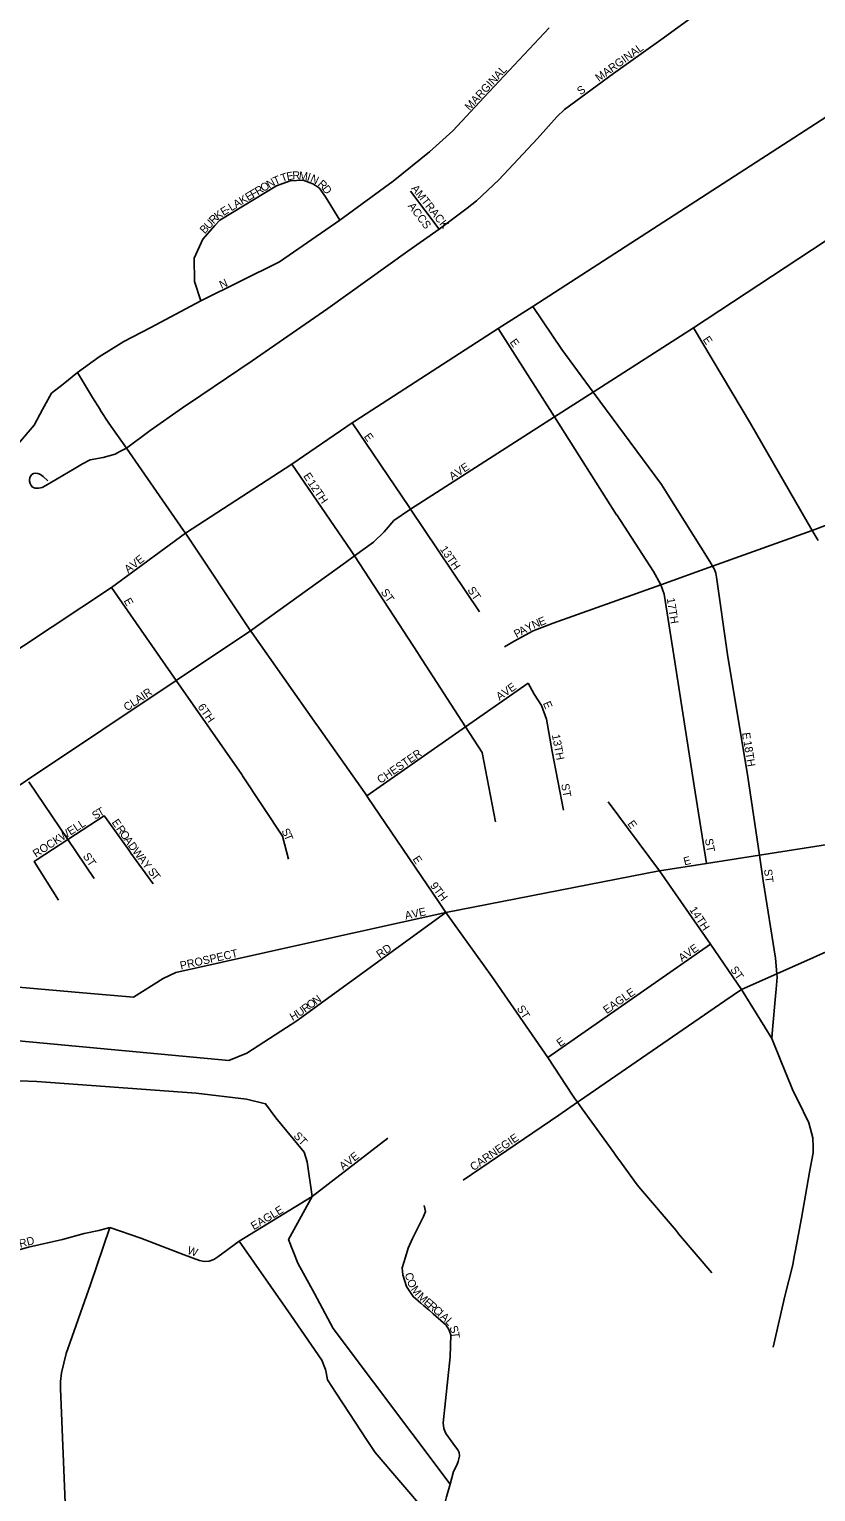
# Model space of a CAD drawing. Extents: x 0 to 96.2, y -27.5 to 31.3.
# Drawn here: x 4.744 to 5.674, y 18.275 to 20.006 of the extents above; entities that cross this region are included whole.
import ezdxf

# ---------------------------------------------------------------- set-up
doc = ezdxf.new("R2010")
doc.units = 0
doc.layers.add('TB_PP_20x10_GRID', color=7, linetype='Continuous')
doc.layers.add('TB_PP_30x10', color=7, linetype='Continuous')

msp = doc.modelspace()

# ---------------------------------------------------------------- linework, layer by layer
at = {"layer": 'TB_PP_20x10_GRID'}
for points in [[(5.1917, 19.7434), (5.2285, 19.7696), (5.2616, 19.7942), (5.2728, 19.8031), (5.2992, 19.828), (5.3449, 19.8768), (5.3677, 19.9026), (5.3768, 19.911), (5.4349, 19.9537), (5.4909, 19.9938), (5.5353, 20.0261)], [(5.3586, 20.0078), (5.282, 19.9258), (5.2448, 19.8858), (5.2172, 19.861), (5.174, 19.8264), (5.1109, 19.7801), (5.0399, 19.7307), (4.9467, 19.6847), (4.8868, 19.6529), (4.8556, 19.6364), (4.8263, 19.6186), (4.8006, 19.5998)], [(5.1289, 19.5424), (5.2984, 19.6518), (5.3392, 19.6781), (5.7386, 19.9359)], [(5.1934, 19.4374), (5.1947, 19.4383), (5.3649, 19.5473), (5.4108, 19.5767), (5.5294, 19.6527), (5.7001, 19.765), (5.8056, 19.8313), (5.8853, 19.8833), (5.8926, 19.888), (5.9149, 19.9019), (5.9668, 19.9359)], [(5.306, 19.2752), (5.3175, 19.2818), (5.3396, 19.294), (5.3633, 19.303), (5.4908, 19.3487), (5.552, 19.3706), (5.6699, 19.4129), (5.8766, 19.4911), (5.987, 19.5341), (6.1189, 19.5852), (6.5959, 19.7707), (6.9729, 19.9173)], [(5.1109, 19.7801), (5.0943, 19.8078), (5.0865, 19.8183), (5.0793, 19.823), (5.0677, 19.8275), (5.0522, 19.8266), (5.0361, 19.8208), (4.9691, 19.7802), (4.9633, 19.7737)], [(5.2285, 19.7696), (5.1947, 19.8145)], [(4.9633, 19.7737), (4.9489, 19.7576), (4.9388, 19.7351), (4.9391, 19.7074), (4.9467, 19.6847)], [(4.9251, 19.5579), (4.9465, 19.5727), (5.0074, 19.6137), (5.097, 19.6756), (5.1917, 19.7434)], [(5.4108, 19.5767), (5.3735, 19.6272), (5.3392, 19.6781)], [(5.4386, 19.4314), (5.4385, 19.4315), (5.3649, 19.5473), (5.2984, 19.6518)], [(5.677, 19.401), (5.6699, 19.4129), (5.5968, 19.5395), (5.5294, 19.6527)], [(4.608, 19.4727), (4.6213, 19.4537), (4.6356, 19.4511), (4.6765, 19.4758), (4.7067, 19.497), (4.7309, 19.5157), (4.7496, 19.5375), (4.7593, 19.5562), (4.7701, 19.5754), (4.784, 19.5861), (4.8006, 19.5998)], [(4.8066, 19.59), (4.8006, 19.5998)], [(4.8281, 19.5551), (4.8274, 19.5562), (4.8187, 19.5703), (4.8066, 19.59)], [(5.4996, 19.4546), (5.4917, 19.4672), (5.4108, 19.5767)], [(4.838, 19.5401), (4.8281, 19.5551)], [(4.8501, 19.5058), (4.8586, 19.5105), (4.8868, 19.5314), (4.9251, 19.5579)], [(4.5743, 19.1717), (4.6662, 19.2297), (4.8411, 19.3455), (4.9286, 19.4096), (5.0545, 19.4913), (5.1255, 19.5402), (5.1289, 19.5424)], [(4.9263, 19.4129), (4.8586, 19.5105), (4.838, 19.5401)], [(5.1928, 19.4411), (5.1255, 19.5402)], [(4.7658, 19.4715), (4.76, 19.4767), (4.76, 19.4768), (4.757, 19.479), (4.7537, 19.4805), (4.7514, 19.4807), (4.7488, 19.4803), (4.7468, 19.4791), (4.7453, 19.4772), (4.7444, 19.4752), (4.7441, 19.4733), (4.7441, 19.4711), (4.7447, 19.4684), (4.7459, 19.4662), (4.7477, 19.4641), (4.7508, 19.4629), (4.755, 19.4628), (4.759, 19.4639), (4.7634, 19.4661), (4.7969, 19.486), (4.8067, 19.4916), (4.8158, 19.4965), (4.8312, 19.4994), (4.8454, 19.5032), (4.8501, 19.5058)], [(5.0545, 19.4913), (5.1246, 19.3888)], [(5.2762, 19.3167), (5.1947, 19.4383), (5.1928, 19.4411)], [(5.6266, 18.8617), (5.6274, 18.8702), (5.6283, 18.8843), (5.628, 18.8881), (5.6265, 18.9067), (5.612, 18.9983), (5.6074, 19.0287), (5.5936, 19.1212), (5.5695, 19.2662), (5.5568, 19.3575), (5.5559, 19.3623), (5.5544, 19.3666), (5.552, 19.3706), (5.5488, 19.376), (5.4996, 19.4546)], [(5.1176, 19.375), (5.1286, 19.383), (5.151, 19.3991), (5.1637, 19.4113), (5.175, 19.4246), (5.1934, 19.4374)], [(5.5073, 19.2573), (5.4948, 19.3376), (5.4908, 19.3487), (5.4906, 19.3493), (5.4822, 19.3645), (5.4386, 19.4314)], [(5.007, 19.2922), (5.0055, 19.2943), (4.9286, 19.4096), (4.9263, 19.4129)], [(5.1246, 19.3888), (5.1286, 19.383), (5.2036, 19.2673)], [(5.0055, 19.2943), (5.1176, 19.375)], [(4.995, 19.1239), (4.9176, 19.2354), (4.8411, 19.3455)], [(4.4808, 18.9427), (4.565, 18.9991), (4.6509, 19.0567), (4.7418, 19.1176), (4.9176, 19.2354), (5.0055, 19.2943)], [(5.0849, 19.1814), (5.0836, 19.1833), (5.007, 19.2922)], [(5.2036, 19.2673), (5.204, 19.2667), (5.2598, 19.1805)], [(5.5303, 19.1108), (5.5073, 19.2573)], [(5.143, 19.0987), (5.2598, 19.1805), (5.3338, 19.2323)], [(5.3756, 19.0818), (5.3624, 19.1512), (5.3557, 19.1897), (5.3498, 19.2057), (5.341, 19.2193), (5.3338, 19.2323)], [(5.1405, 19.1022), (5.0865, 19.1791), (5.0849, 19.1814)], [(5.2598, 19.1805), (5.2795, 19.1502), (5.2954, 19.0679)], [(4.8205, 19.001), (4.7894, 19.0472), (4.7433, 19.1154)], [(5.0504, 19.0238), (5.0434, 19.0509), (4.996, 19.1226), (4.995, 19.1239)], [(5.5447, 19.0189), (5.5303, 19.1108)], [(5.1787, 19.0462), (5.1443, 19.0967), (5.143, 19.0987), (5.1405, 19.1022)], [(5.5863, 18.8695), (5.5496, 18.9233), (5.4892, 19.0102), (5.4285, 19.0916)], [(4.8337, 19.0733), (4.8323, 19.0752), (4.7894, 19.0472), (4.7531, 19.0236)], [(4.8619, 19.034), (4.8337, 19.0733)], [(5.4887, 19.0101), (5.4892, 19.0102), (5.5447, 19.0189), (5.6074, 19.0287), (5.7659, 19.0535), (5.8206, 19.062)], [(5.2287, 18.9725), (5.1787, 19.0462)], [(4.7531, 19.0236), (4.7496, 19.0213), (4.7782, 18.9755)], [(4.8901, 18.9946), (4.8639, 19.0311), (4.8619, 19.034)], [(5.078, 18.9257), (5.2366, 18.9608), (5.4887, 19.0101)], [(5.3862, 18.7445), (5.3571, 18.7892), (5.2909, 18.8849), (5.2366, 18.9608), (5.2287, 18.9725)], [(5.0634, 18.8349), (5.2366, 18.9608)], [(4.9021, 18.8825), (4.9169, 18.8899), (5.078, 18.9257)], [(5.3571, 18.7892), (5.5496, 18.9233)], [(5.3946, 18.7378), (5.5667, 18.8561), (5.5863, 18.8695), (5.628, 18.8881), (5.7182, 18.9282), (5.7299, 18.9337)], [(4.6455, 18.8834), (4.6634, 18.8781), (4.8069, 18.8658)], [(4.8069, 18.8658), (4.8672, 18.8607), (4.9021, 18.8825)], [(5.622, 18.8115), (5.6137, 18.825), (5.5863, 18.8695)], [(5.622, 18.8115), (5.623, 18.8224), (5.6266, 18.8617)], [(5.0479, 18.8246), (5.0604, 18.8327), (5.0634, 18.8349)], [(4.5662, 18.8241), (4.9798, 18.7855), (5.0011, 18.7941)], [(5.0011, 18.7941), (5.0479, 18.8246)], [(5.6407, 18.7658), (5.6336, 18.7832), (5.622, 18.8115)], [(5.671, 18.6829), (5.6708, 18.6942), (5.666, 18.7119), (5.6529, 18.7385), (5.6475, 18.7491), (5.645, 18.7552), (5.6407, 18.7658)], [(4.5436, 18.7057), (4.5862, 18.7359), (4.6832, 18.7567), (4.7123, 18.7622), (4.7525, 18.7608), (4.941, 18.747), (5.0005, 18.74), (5.0233, 18.7344), (5.0355, 18.7177), (5.0687, 18.677), (5.0723, 18.6657), (5.0784, 18.6246), (5.0504, 18.5737), (5.0615, 18.5459), (5.0812, 18.5098), (5.1031, 18.4683), (5.1509, 18.4047), (5.2415, 18.2842)], [(5.2568, 18.6438), (5.37, 18.7209), (5.3921, 18.7361), (5.3946, 18.7378)], [(5.4374, 18.6731), (5.4351, 18.6765), (5.4124, 18.7081), (5.3977, 18.7284), (5.3921, 18.7361), (5.3886, 18.7409), (5.3862, 18.7445)], [(4.9269, 18.5556), (4.9449, 18.5487), (4.9506, 18.5477), (4.9567, 18.5479), (4.9621, 18.5499), (4.9668, 18.5532), (4.9922, 18.5716), (5.0784, 18.6246), (5.1677, 18.6936)], [(5.6237, 18.4463), (5.6375, 18.5066), (5.6468, 18.5437), (5.6487, 18.5536), (5.6497, 18.5593), (5.6571, 18.5991), (5.6668, 18.6536), (5.6711, 18.6761), (5.671, 18.6829)], [(5.4692, 18.6311), (5.4629, 18.6385), (5.4441, 18.6639), (5.4374, 18.6731)], [(5.551, 18.5341), (5.5118, 18.5805), (5.5088, 18.5842), (5.4692, 18.6311)], [(5.2109, 18.6139), (5.2123, 18.6067), (5.2102, 18.6008), (5.1971, 18.575), (5.1921, 18.5635), (5.1888, 18.553), (5.1847, 18.5401), (5.1858, 18.5317), (5.19, 18.5181), (5.1979, 18.5062), (5.2068, 18.4984), (5.2104, 18.4953), (5.2162, 18.4903), (5.2215, 18.4857), (5.2368, 18.4724), (5.2402, 18.4672), (5.2422, 18.4609), (5.2415, 18.4348), (5.2334, 18.3567), (5.234, 18.35), (5.2364, 18.344), (5.248, 18.3283), (5.2506, 18.3247), (5.2521, 18.3218), (5.2524, 18.3205), (5.2527, 18.3188), (5.2526, 18.3172), (5.2523, 18.3156), (5.2511, 18.311), (5.2495, 18.3066), (5.2455, 18.299), (5.2415, 18.2842)], [(4.6708, 18.5444), (4.7429, 18.5647), (4.7832, 18.5736), (4.8087, 18.581), (4.8259, 18.5842), (4.8392, 18.588)], [(4.7867, 17.6939), (4.7863, 17.7245), (4.7771, 17.8376), (4.7736, 17.8561), (4.7785, 17.9483), (4.7867, 18.0987), (4.7877, 18.1227), (4.789, 18.1413), (4.7887, 18.1703), (4.7874, 18.2006), (4.7864, 18.2526), (4.7807, 18.3972), (4.7807, 18.4056), (4.782, 18.416), (4.7875, 18.4389), (4.816, 18.5206), (4.8392, 18.588)], [(4.8392, 18.588), (4.8757, 18.5754), (4.9269, 18.5556)], [(5.0948, 18.4164), (5.0941, 18.42), (5.0896, 18.4307), (5.053, 18.4842), (5.0468, 18.4931), (4.9922, 18.5716)], [(5.1428, 18.3371), (5.1227, 18.3678), (5.1068, 18.392), (5.0965, 18.4077), (5.0948, 18.4164)], [(5.2135, 18.2505), (5.1529, 18.3218), (5.1428, 18.3371)], [(5.2415, 18.2842), (5.2415, 18.2842), (5.2373, 18.2692), (5.236, 18.2643), (5.2342, 18.2603), (5.2313, 18.2573), (5.2274, 18.2549), (5.2135, 18.2505)]]:
    msp.add_lwpolyline(points, dxfattribs=at)

# ---------------------------------------------------------------- texts
at = {"layer": 'TB_PP_30x10'}
for s, rotation, p in [('MARGINAL', 35.8036, (5.4175, 19.9437)), ('MARGINAL', 47.3667, (5.2647, 19.9092)), ('S', 35.5436, (5.3958, 19.9278)), ('E', 10.6348, (5.0489, 19.8271)), ('R', 2.3081, (5.0551, 19.8283)), ('M', 353.1348, (5.0622, 19.8286)), ('R', 30.9372, (5.0141, 19.8094)), ('O', 30.9188, (5.0205, 19.8133)), ('N', 29.734, (5.0276, 19.8176)), ('T', 23.0443, (5.0346, 19.8216)), ('T', 19.1173, (5.0429, 19.825)), ('I', 342.3253, (5.0716, 19.8275)), ('N', 334.7058, (5.0753, 19.8263)), ('R', 317.594, (5.0843, 19.8219)), ('D', 307.4687, (5.0895, 19.8171)), ('AMTRACK', 308.5293, (5.1949, 19.8175)), ('A', 30.9188, (4.9884, 19.794)), ('K', 30.926, (4.9955, 19.7983)), ('E', 30.9378, (5.0027, 19.8026)), ('F', 30.931, (5.0084, 19.806)), ('R', 46.563, (4.962, 19.7751)), ('K', 36.2186, (4.9668, 19.7802)), ('E', 31.1887, (4.9734, 19.785)), ('-', 30.8888, (4.9791, 19.7885)), ('L', 30.9321, (4.9826, 19.7906)), ('ACCS', 307.1845, (5.1911, 19.7968)), ('B', 47.5418, (4.9513, 19.7634)), ('U', 47.5498, (4.9564, 19.7689)), ('N', 23.9738, (4.9711, 19.6988)), ('E', 305.5436, (5.3116, 19.6357)), ('E', 303.6733, (5.54, 19.639)), ('E', 305.5436, (5.1391, 19.5241)), ('AVE', 33.6901, (5.2442, 19.472)), ('E', 303.6985, (5.0675, 19.4774)), ('12TH', 304.6965, (5.0725, 19.4691)), ('13TH', 304.6965, (5.2291, 19.3907)), ('AVE', 38.0509, (4.8607, 19.3619)), ('ST', 304.6987, (5.1591, 19.3399)), ('ST', 304.6908, (5.2616, 19.3424)), ('E', 299.755, (4.8551, 19.3298)), ('17TH', 278.8832, (5.4978, 19.3325)), ('Y', 26.7508, (5.3333, 19.2926)), ('N', 23.2589, (5.3406, 19.2963)), ('E', 22.8111, (5.3482, 19.2995)), ('P', 28.545, (5.3201, 19.2854)), ('A', 28.5494, (5.326, 19.2886)), ('AVE', 35.3165, (5.3, 19.2112)), ('CLAIR', 33.9939, (4.8592, 19.1987)), ('6TH', 304.5935, (4.9425, 19.2041)), ('E', 293.2569, (5.3511, 19.2084)), ('13TH', 280.6213, (5.3619, 19.1709)), ('E', 277.1217, (5.5869, 19.1733)), ('18TH', 279.1648, (5.5886, 19.1633)), ('CHESTER', 34.4594, (5.1592, 19.1128)), ('ST', 280.6147, (5.3728, 19.1125)), ('S', 32.7582, (4.8217, 19.0703)), ('T', 29.6093, (4.8271, 19.0739)), ('ROCKWELL', 32.8703, (4.7517, 19.0254)), ('E', 304.7055, (4.8408, 19.0674)), ('R', 304.7274, (4.846, 19.0598)), ('S', 298.1416, (5.0417, 19.0573)), ('E', 305.5436, (5.4508, 19.0657)), ('O', 304.7145, (4.8503, 19.0537)), ('A', 304.7145, (4.855, 19.0468)), ('D', 305.7592, (4.8599, 19.0398)), ('T', 292.395, (5.0447, 19.0517)), ('ST', 280.6279, (5.5428, 19.0475)), ('ST', 304.6987, (4.8066, 19.0274)), ('W', 307.7272, (4.865, 19.0328)), ('A', 307.8744, (4.8716, 19.0242)), ('E', 303.6985, (5.1967, 19.024)), ('E', 14.0491, (5.5189, 19.0164)), ('Y', 307.8903, (4.8767, 19.0176)), ('S', 307.8716, (4.8834, 19.0091)), ('T', 307.8889, (4.8875, 19.0038)), ('ST', 277.1351, (5.6128, 19.0116)), ('9TH', 306.8682, (5.2174, 18.9924)), ('AVE', 12.0958, (5.189, 18.9523)), ('14TH', 303.6957, (5.5242, 18.964)), ('RD', 34.5143, (5.1583, 18.9062)), ('AVE', 35.3105, (5.5158, 18.902)), ('PROSPECT', 12.6186, (4.9231, 18.8931)), ('ST', 304.7022, (5.5725, 18.8932)), ('EAGLE', 34.8271, (5.4267, 18.8403)), ('R', 36.0182, (5.0701, 18.8417)), ('O', 36.0495, (5.0761, 18.8461)), ('N', 36.0306, (5.0829, 18.851)), ('ST', 302.7321, (5.32, 18.8473)), ('H', 30.2139, (5.0552, 18.8321)), ('U', 35.1333, (5.0631, 18.8368)), ('E', 35.5436, (5.3716, 18.8012)), ('ST', 312.5121, (5.0557, 18.6959)), ('CARNEGIE', 34.5918, (5.2692, 18.6545)), ('AVE', 38.0509, (5.1149, 18.6553)), ('EAGLE', 31.1382, (5.0093, 18.5846)), ('RD', 14.7447, (4.733, 18.5639)), ('W', 341.5596, (4.9299, 18.5572)), ('C', 283.5061, (5.1879, 18.5333)), ('O', 292.9245, (5.1901, 18.5244)), ('M', 306.1702, (5.1946, 18.5146)), ('M', 318.6731, (5.202, 18.5049)), ('E', 320.0084, (5.2097, 18.4981)), ('R', 318.7638, (5.2147, 18.4939)), ('C', 318.4874, (5.2204, 18.489)), ('I', 318.4645, (5.226, 18.484)), ('A', 318.4766, (5.2291, 18.4812)), ('L', 313.1835, (5.2352, 18.4759)), ('S', 291.9181, (5.2404, 18.4696)), ('T', 276.488, (5.2428, 18.464))]:
    msp.add_text(s, height=0.00947, rotation=rotation, dxfattribs=at).set_placement(p)

doc.saveas('drawing.dxf')
